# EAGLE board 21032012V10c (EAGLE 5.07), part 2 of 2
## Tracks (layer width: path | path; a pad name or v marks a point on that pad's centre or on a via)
ADJ2  (via drill 1)
  Top 0.406: 22.23,62.23 V-SO8.4 21.78,63.65 | 31.55,74.3 33.02,74.93 | V-1083.1 36.17,74.24 35.56,82.23 33.28,84.75 C-MABDT1.1 | V-TO3.2 19.68,74.3
  Top 0.813: 22.23,62.23 TO92S.1 | 21.78,63.65 VR6.2 19.2,63.65 18.41,62.87 16.75,62.87 VPOT1.S | 33.28,84.75 VC2X.+
  Top 1.27: v40.64,74.61 39.37,73.03 | 19.68,74.3 31.55,74.3 | v22.37,76.39 V-TO3.2
  Bottom 0.406: 39.91,72.3 V-1083.1 V-TS.1 | 39.91,72.3 39.37,72.83 | 39.91,72.3 40.64,73.03 v40.64,74.61 41.27,74.93
  Bottom 0.813: VPOT1.S VPOT2.S 17.46,62.55 18.35,63.44
  Bottom 1.27: 18.35,63.44 arc30 22.23,73.66 v22.37,76.39
  pour Bottom (isolate 0.813, hatched): 39.37,76.83 43.18,76.83 43.18,69.22 41.91,67.94 39.37,67.94
  pour Top (isolate 0.813, hatched): 43.18,76.83 43.18,69.22 42.55,68.58 40.01,68.58 39.37,69.22 arc23 34.92,73.03 29.21,74.3 34.29,76.2 34.29,78.11 33.34,88.27 36.83,86.36 36.83,78.74 38.73,76.83
ADJUST  (via drill 0.6, 1)
  Top 0.406: 27.53,37.21 CR2.1 | V-TO1.2 19.22,34.29 v17.72,32.07 18.41,31.11 | 29.21,36.83 C-SO8.4 | 29.21,35.56 29.21,36.83 | 9.62,31.68 8.98,31.68 C.A | C.A C..A A.A 6.35,31.11 CD31.A | 29.21,36.83 28.57,36.83 | 29.21,35.56 29.21,33.66 | C-TO92.1 29.21,35.56 | CD4.1 10.96,29.68 9.53,31.11 9.53,31.14 C.A
  Top 0.813: C-1083.1 35.63,34.87 C.1.A | C-MABDT.1 31.49,47.25 33.66,45.09 33.66,42.55 C.1.A | C.1.A 36.65,41.27 38.73,41.27 38.99,41.02 C_REG_Q.E
  Top 1.016: 27.53,37.21 28.57,37.21 28.57,36.83
  Top 1.27: v29.21,28.26 26.67,28.51 arc-33 18.41,31.11
  Bottom 0.406: C-1083.1 39.5,32.38 | 29.72,33.85 C-TO92.1
  Bottom 0.813: 29.72,30.54 29.72,33.85
  Bottom 1.27: C-TS.1 C-1083.1 39.37,31.75 37.47,31.75 arc37 29.91,29.34 29.72,29.15 | v29.21,28.26 29.21,28.64 29.72,29.15 | 29.72,29.15 29.72,30.54
  pour Bottom (isolate 0.813, hatched): 19.68,32.38 arc-90 17.78,30.48 4.45,30.48 3.81,31.75 3.81,33.66 5.08,34.92 10.79,34.92 11.43,35.56 19.68,35.56
  pour Top (isolate 0.61): 29.84,39.37 20.95,39.37 20.95,36.83 28.57,36.2 29.21,35.56 29.84,35.56
B
  Top 0.406: VR48.1 78.72,15.9 | VR48.1 78.75,14.59 79.38,13.97 TRIM10X.S | VR48.1 VR47.2 VR49.2 | Q14.B 73.97,25.72 74.3,25.4 74.3,20.95 74.93,20.32 75.56,20.32 76.2,19.68 76.2,18.41 77.47,17.14 77.47,16.2 VR48.1
B1
  Bottom 0.406: 42.55,8.89 44.07,9.97 44.07,35.37 42.55,36.2 42.16,36.2 C_REG_Q.B
  Bottom 0.61: 42.55,8.89 33.66,8.89 32.38,7.62 27.94,7.62 26.67,8.89 13.97,8.89 11.43,11.43 CTRIM3.S R22.S
B-Q1
  Top 0.406: FC5.2 267.33,22.71 Q4.B 266.06,24.62 266.06,29.21 266.7,29.84 R8.2
BATT-  (via drill 0.6)
  Top 0.406: PS16.2 67,92.88 66.84,92.88 66.04,92.08 66.04,90.94 PS_TOP.2 65.91,88.39 v66.04,88.27 | v84.45,91.44 PS_ZEN_FB.A | P_Q11.2 v114.3,79.5 114.3,80.64 113.44,81.51 P_Q2.3 | P_C6.A 105.12,89.34 P_C10.- | v273.37,23.5 273.69,22.86 273.69,19.68 272.73,18.73 T1.2 272.73,15.4 FR12.2 | VENT_RB.2 103.35,79.86 v102.23,78.74 D11.A | D41.A 258.44,6.99 MINUS0S.1 | Q23.3 252.47,42.8 252.73,42.55 Q28.E | DR15.A 152.88,84.61 153.03,84.45 154.31,84.45 155.57,83.19 155.57,81.92 156.21,81.28 158.62,81.28 DC7.2
  Top 0.61: IC1.8 U$2.2 | DISP_Z.A 121.49,80.85 120.02,79.38 114.43,79.38 v114.3,79.5
  Bottom 0.406: v66.04,88.27 66.04,81.28 67.31,80.64 84.45,80.64 v84.45,91.44 | 114.3,80.64 118.75,80.64 118.75,79.38 121.28,76.83 263.52,76.83 | 114.3,80.64 106.05,80.64 | 106.05,80.64 102.23,80.64 v102.23,78.74 | 114.3,80.64 v114.3,79.5 | P_C10.- 106.05,89.53 106.05,80.64 | 149.22,94.61 IC1.8 151.76,92.71 152.4,92.08 163.83,92.08 165.53,93.78 SP1.- | 149.22,94.61 149.22,88.27 147.61,86.65 DR15.A | 149.22,94.61 146.05,94.61 C9.- 144.15,93.98 142.88,92.71 | 263.52,23.5 v273.37,23.5
  Bottom 0.813: 102.23,80.64 84.45,80.64
  Bottom 1.27: MINUS0X1.1 MINUS0S.1
  Bottom 1.778: Q44.E Q28.E
  Bottom 2.54: S1.5 197.49,97.79 211.46,83.82 255.27,83.82 | MINUS60.1 256.62,95.33 255.27,93.34 255.27,83.82 | 255.27,83.82 263.52,76.83 263.52,23.5 263.52,9.53 260.35,6.35 MINUS0S.1 257.81,7.62 257.81,37.21 Q44.E
  pour Top (isolate 0.813): 252.09,44.45 255.91,44.45 257.81,42.55 257.81,36.83 257.18,36.2 252.73,36.2 252.09,36.83 252.09,43.81
  pour Bottom (isolate 0.813, rank 2, hatched): 64.77,97.16 64.77,80.64 66.67,78.74 168.91,78.74 170.18,80.01 170.18,98.42 168.91,99.69 67.31,99.69 65.41,97.79
D
  Top 1.27: F2.1B 270.76,50.55 R6.2 | Q5.3 R6.2 | R6.2 268.22,50.8 F2.1A
E2  (via drill 0.6)
  Top 0.406: 243.21,8.26 243.21,6.99 MINU1S.1 241.3,5.71 239.4,7.62 D23.A | 243.21,8.26 D48.C | VR45.1 243.21,8.26 | LED11.A 250.82,27.3 R24.2 | Q7.3 233.42,42.8 233.68,42.55 Q18.E
  Top 0.61: Q37.E 242.89,27.62 v242.57,27.94
  Bottom 0.61: v242.57,27.94 242.57,27.3 244.79,25.08
  Bottom 1.27: MINU1S.1 MINUS1X.1
  Bottom 1.778: Q43.E Q18.E
  Bottom 2.54: R24.2 247.01,27.3 244.79,25.08 243.84,24.13 243.84,8.26 241.3,5.71 | MINU1S.1 241.3,5.71 | Q43.E 236.85,39.37 238.76,37.47 238.76,7.62 239.4,6.99 240.03,6.99 241.3,5.71
  pour Top (isolate 0.813): 233.04,44.45 236.85,44.45 238.76,42.55 238.76,36.83 238.12,36.2 233.68,36.2 233.04,36.83 233.04,43.81
E3  (via drill 0.6)
  Top 0.406: VR34.1 225.43,8.26 224.16,6.99 | D39.A 220.34,6.99 MINUS2.1 224.16,6.99 | Q24.3 214.37,42.8 214.63,42.55 Q27.E | LED6.A 231.78,26.67 R18.2 | 224.16,6.99 D30.C
  Top 0.61: Q36.E 223.84,27.62 v223.52,27.94
  Bottom 0.61: 226.06,25.4 v223.52,27.94
  Bottom 1.27: MINUS2.1 MINUS2X1.1
  Bottom 1.778: Q42.E Q27.E
  Bottom 2.54: R18.2 227.97,27.3 226.06,25.4 224.79,24.13 224.79,8.89 222.25,6.35 MINUS2.1 219.71,7.62 219.71,37.47 217.81,39.37 Q42.E
  pour Top (isolate 0.813): 214,44.45 217.81,44.45 219.71,42.55 219.71,36.83 219.07,36.2 214.63,36.2 214,36.83 214,43.81
E4  (via drill 0.6)
  Top 0.406: 205.74,8.26 D46.C | 203.2,5.71 205.74,8.26 | 205.74,8.26 VR44.1 | D21.A 201.29,7.62 203.2,5.71 | MINUS3S.1 203.2,5.71 | Q8.3 195.32,42.8 195.58,42.55 Q17.E | LED10.A 212.72,26.67 R21.2
  Top 0.61: Q35.E 204.79,27.62 v204.47,27.94
  Bottom 0.61: v204.47,27.94 205.1,27.94 207.33,25.72
  Bottom 1.27: MINUS3X.1 MINUS3S.1
  Bottom 1.778: Q41.E Q17.E
  Bottom 2.54: R21.2 208.91,27.3 207.33,25.72 205.74,24.13 205.74,8.26 203.2,5.71 MINUS3S.1 200.66,7.62 200.66,37.47 198.75,39.37 Q41.E
  pour Top (isolate 0.813): 194.94,44.45 198.75,44.45 200.66,42.55 200.66,36.83 200.03,36.2 195.58,36.2 194.94,36.83 194.94,43.81
E5  (via drill 0.6)
  Top 0.406: LED5.A 193.04,25.25 R16.2 | VR33.1 186.69,8.26 186.37,7.94 | 186.37,7.94 184.15,5.71 MINUS4S.1 184.15,6.99 182.25,8.89 D37.A | D28.C 186.37,10.68 186.37,7.94 | Q25.3 176.27,42.8 176.53,42.55
  Top 0.61: Q34.E 186.38,27.62 v186.06,27.94
  Bottom 0.61: 188.28,25.72 v186.06,27.94
  Bottom 1.27: MINUS4X4.1 MINUS4S.1
  Bottom 1.778: Q40.E Q26.E
  Bottom 2.54: R16.2 189.87,27.3 188.28,25.72 186.69,24.13 186.69,8.26 184.78,6.35 184.78,5.71 MINUS4S.1 181.61,7.62 181.61,37.47 179.71,39.37 Q40.E
  pour Top (isolate 0.813): 175.9,44.45 179.71,44.45 181.61,42.55 181.61,36.83 180.97,36.2 176.53,36.2 175.9,36.83 175.9,43.81
E6  (via drill 0.6)
  Top 0.406: LED9.A 173.99,24.61 R13.2 | Q9.3 157.22,42.8 157.48,42.55 | Q33.E 167.32,28.25 v167,28.57
  Top 0.61: D19.A 163.19,6.99 MINUS5S.1 167.64,7.62 167.64,8.26 | 167.64,8.26 D44.C | 167.64,8.26 VR46.1
  Bottom 0.406: v167,28.57 167.64,28.57 169.54,26.67 173.35,26.67 R13.2
  Bottom 1.27: MINUS5X2.1 MINUS5S.1
  Bottom 1.778: Q39.E Q16.E
  Bottom 2.54: R13.2 170.81,27.3 167.64,24.13 167.64,8.26 166.37,6.99 165.74,6.99 165.1,6.35 MINUS5S.1 162.56,7.62 162.56,37.47 160.66,39.37 Q39.E
  pour Top (isolate 0.813): 156.84,44.45 160.66,44.45 162.56,42.55 162.56,36.83 161.93,36.2 157.48,36.2 156.84,36.83 156.84,43.81
E7  (via drill 0.6)
  Top 0.406: LED4.A 154.94,24.61 R14.2
  Top 0.61: Q32.E 148.28,27.62 v147.96,27.94 | D34.A 144.15,6.99 MINUS6S.1 149.22,8.26 | 149.22,8.26 D26.C | 149.22,8.26 VR35.1
  Bottom 0.61: 150.18,25.72 v147.96,27.94
  Bottom 1.27: MINUS6X2.1 MINUS6S.1
  Bottom 1.778: Q38.E Q22.E
  Bottom 2.54: R14.2 151.76,27.3 150.18,25.72 148.59,24.13 148.59,8.26 MINUS6S.1 143.51,7.62 143.51,37.47 141.6,39.37 Q38.E
  pour Top (isolate 0.813): 137.79,44.45 141.6,44.45 143.51,42.55 143.51,36.83 142.88,36.2 138.43,36.2 137.79,36.83 137.79,43.81
E8  (via drill 0.6)
  Top 0.406: D13.C 125.09,6.99 PLUS7+.1 129.54,7.62 129.54,8.26 | 129.54,8.26 D35.C | 129.54,8.26 VR36.1 | LED7.A 135.89,24.61 R5.2 | Q3.3 119.12,42.8 119.38,42.55
  Top 0.61: Q31.E 129.22,27.62 v128.91,27.94
  Bottom 0.61: 131.13,25.72 v128.91,27.94
  Bottom 1.27: MINUS8-.1 PLUS7+.1
  Bottom 1.778: Q21.E Q15.E
  Bottom 2.54: R5.2 132.72,27.3 131.13,25.72 129.54,24.13 129.54,7.62 PLUS7+.1 125.09,6.99 124.46,6.99 124.46,37.47 122.56,39.37 Q21.E
  pour Top (isolate 0.813): 118.75,44.45 122.56,44.45 124.46,42.55 124.46,36.83 123.83,36.2 119.38,36.2 118.75,36.83 118.75,43.81
E9  (via drill 0.6)
  Top 0.406: D18.A 106.05,7.62 MINUS9.1 110.49,7.62 110.49,8.26 | LED8X.A 117.47,26.67 R4.2 | 110.49,8.26 D14.C | 110.49,8.26 VR28.1 | Q2T.E 100.07,39.63
  Top 0.61: Q30.E 110.17,27.62 v109.86,27.94
  Bottom 0.61: v109.86,27.94 109.86,27.3 111.76,25.4
  Bottom 1.27: PLUS8+.1 MINUS9.1
  Bottom 1.778: Q2T.E Q29.E 103.5,39.37
  Bottom 2.54: R4.2 113.67,27.3 111.76,25.4 110.49,24.13 110.49,8.26 108.58,6.35 108.58,5.71 MINUS9.1 105.41,7.62 105.41,37.47 103.5,39.37
  pour Top (isolate 0.813): 99.69,44.45 103.5,44.45 105.41,42.55 105.41,36.83 104.78,36.2 100.33,36.2 99.69,36.83 99.69,43.81
GATE
  Top 0.406: Q5.1 268.23,35.78 R10.2 269.72,33.81 270.51,33.02 270.51,29.84 269.88,29.21 269.88,28.09 R9.1 269.24,27.94 268.61,27.3 Q4.C
HOT  (via drill 0.6)
  Top 0.406: Q6.C Q10.2 92.71,86.36 93.34,87 95.25,87 97.16,88.9 v97.16,89.53 P_L1.1 99.39,89.58 P_C6.C
  pour Top (isolate 0.813, hatched): 95.25,92.08 99.06,92.08 100.33,90.81 100.33,84.45 99.69,83.82 93.98,83.82 92.08,85.72 90.81,85.72 90.81,86.36 90.81,87 92.71,87 94.61,88.9 94.61,89.53 95.25,90.17
  pour Bottom (isolate 0.813, hatched): 95.25,92.08 99.06,92.08 100.33,90.81 100.33,84.45 99.69,83.82 93.98,83.82 92.08,85.72 90.81,85.72 90.81,86.36 90.81,87 92.71,87 94.61,88.9 94.61,89.53 95.25,90.17
IN+1
  Top 0.406: 25.1,82.22 V-TO3.1 31.11,81.28 C-MABDT1.3 | TO92S.3 26.04,62.23 26.04,63.5 V-SO8.1
  Top 0.813: 26.04,59.05 26.04,63.5
  pour Bottom (isolate 0.813, hatched): 43.18,64.14 43.18,59.05 36.07,58.93 37.34,64.01
  pour Top (isolate 0.813, rank 3, hatched): 26.67,100.33 26.67,88.27 30.8,85.72 32.7,78.74 21.59,78.74 18.41,76.83 18.41,71.75 26.04,71.75 29.53,66.74 30.35,65.91 arc139 40.64,64.14 43.18,64.14 43.18,59.05 27.3,59.05 26.04,58.42 26.04,64.14 arc90 22.23,67.94 18.1,68.26 15.24,70.17 15.24,80.01 17.14,81.92 19.68,82.55 arc32 23.5,100.33
  pour Bottom (isolate 0.813, rank 4): 29.21,79.38 15.88,79.38 15.88,81.28 19.68,85.09 23.5,100.97 26.67,100.97 26.67,87 27.94,85.72 31.75,85.72 31.75,80.64
IN-  (via drill 1.3)
  Top 2.54: v203.84,111.12 v40.64,111.12
  Bottom 0.406: 45.72,92.71 VR10.2 43.18,95.89 VIN(-).1
  Bottom 2.54: MINUS120.1 217.88,97.08 v203.84,111.12 | v40.64,111.12 VIN(-).1
  pour Bottom (isolate 0.813, rank 2): 35.56,100.97 46.35,100.97 47.62,98.42 47.62,90.81 35.56,90.81
  pour Top (isolate 0.813, hatched): 47.62,100.33 47.62,88.9 38.73,88.9 38.73,93.98 35.56,94.61 35.56,100.33
INPUT+  (via drill 1)
  Top 0.406: C-SO8.1 32.7,40.96 v30.54,41.91 V-TO1.1 | CC3.1 CD1.C | C-TO92.3 33.02,35.56 | C-SO8.1 33.02,38.73 | 33.02,38.1 C-SO8.1 | v30.48,49.78 C-MABDT.3
  Top 0.61: C_OPTN1.1 37.47,51.44
  Top 0.813: 33.02,38.1 33.02,35.56 33.02,33.66 | 37.47,51.44 C_HV_Q.E
  Bottom 1.27: C-1083.3 C-TS.3
  pour Top (isolate 0.61, rank 2, hatched): 33.66,52.7 26.67,52.7 26.04,44.45 21.59,44.45 21.59,40.64 22.86,40.64 23.5,40.01 31.75,40.01 31.75,39.37 33.66,39.37
  pour Bottom (isolate 0.813, rank 2, hatched): 43.18,50.8 33.02,52.7 27.94,52.7 27.94,46.35 20.95,41.27 20.95,38.73 22.86,36.83 22.86,34.29 20.95,31.11 20.95,20.32 29.84,20.32 37.47,16.51 41.27,16.51 41.27,23.5 31.11,23.5 25.4,27.3 25.4,37.47 26.67,38.73 33.66,41.27 33.66,48.26 43.18,48.9
  pour Top (isolate 0.813, rank 2): 38.1,20.32 42.55,20.32 42.55,8.26 38.1,8.26
MINUS
  Top 0.406: CTRIM3.A 16.38,12.7 8.89,12.7 8.43,13.16 8.45,20.13 8.45,23.05 8.89,23.5 CD49.C 9.32,24.97 10.16,24.13 10.64,24.13 CD4.2
  Bottom 0.406: R22.E 16.43,12.73 CTRIM3.A
N$1
  Bottom 0.406: 16.43,60.01 VPOT2.A | VPOT1.E 17.27,58.55
  Bottom 1.016: VPOT1.E 16.43,60.01
  Bottom 1.27: 17.27,58.55 V_OPTION.2
N$2
  Top 0.406: VR5.2 16.43,66.04 VPOT1.A 14.35,66.61 arc-135 13.34,71.75 VR4.2
  Bottom 0.813: 16.45,66.4 VPOT1.A
  Bottom 1.27: VPOT2.E 16.45,66.4
N$3
  Top 0.406: VTRIM1.E VR8.2
  Bottom 0.813: VTRIM1.E 28.89,76.83
  pour Bottom (isolate 0.813, rank 2, hatched): 32.38,78.11 32.38,76.2 33.34,74.93 27.3,74.93 26.67,75.56 26.67,78.11
N$4
  Bottom 0.406: VR1.1 28.85,69.53 28.85,71.16
  Bottom 0.813: 28.85,71.16 VTRIM1.A
  pour Bottom (isolate 0.813, rank 3, hatched): 32.38,73.66 31.11,69.22 29.21,67.31 26.67,67.94 26.67,73.03 27.3,73.66
N$5
  Bottom 0.406: 17.73,18.41 CTRIM3.E 16.43,17.75 R22.A
  Bottom 0.61: 21,17.74 19.68,18.41 17.73,18.41
  Bottom 0.813: CTRIM2.A 24.13,12.74 CTRIM2.S 21.59,17.14 21,17.74
N$6
  Top 0.813: CR3.1 24.2,20.17 CTRIM2.E
N$7
  Top 0.406: VR7.1 VR3.1
  Bottom 0.406: VR3.1 VC1.1 VC2.2
  pour Bottom (isolate 0.813, rank 3): 34.29,90.81 27.3,90.81 27.3,100.97 34.29,100.97
  pour Top (isolate 0.813, rank 4): 34.29,90.81 27.3,90.81 27.3,100.33 34.29,100.33
N$9
  Bottom 0.813: CC4.- 31.75,11.43 VIN(-)1.1
  pour Bottom (isolate 0.813): 28.57,14.61 37.47,14.61 37.47,9.53 33.66,9.53 32.38,8.26 29.21,8.26 28.57,8.89
  pour Top (isolate 0.813): 28.57,14.61 37.47,14.61 37.47,8.26 29.21,8.26 28.57,8.89
N$10
  Top 0.813: V_HV_Q.B 19.05,96.67 VR9.1 VD5.C
N$11
  Top 0.406: OK10X.2 87,22.23 86.36,22.86 83.82,22.86 82.55,21.59 82.55,21.44 VR14.1 79.7,20.8 LED10X.C
N$12
  Top 0.406: VR3.2 VR7.2 29.88,87.83 VD7.C
  Top 0.813: VR2.1 VR8.1 | V_OPTION.1 VR6.1
  Bottom 0.813: VR3.2 30.42,85.79 33.66,84.45 VR2.1 33.66,76.47 arc-77 22.29,63.06 21.78,63.06 20.38,61.59 V_OPTION.1
N$13
  Top 0.406: VD6.C 31.75,92.08 VD7.A
N$14
  Top 0.406: D10A.A 74.72,16.4 VR48.2 75.25,13.65 TRIM10X.A
N$15
  Top 0.406: Q14.C 73.03,22.38 VR11.1
N$16
  Top 0.406: VR28.2 121.92,8.26 123.19,9.53 123.19,15.24 123.83,15.88 123.83,19.36 OK8X.1
N$17
  Top 0.406: D10A.C 71.33,15.46 D10.A
N$18
  Top 0.406: T1.3 271.78,24.77 272.42,25.4 272.42,27.79 R9.2
N$19
  Top 0.406: R11.1 272.57,10.31 271.78,9.53 267.97,9.53 267.33,10.16 FD16.A
N$20
  Top 0.406: TRIM9X.A 95.25,12.06 93.98,13.34 93.98,15.55 VR51.1 94.3,17.89 D9A.A
N$21
  Top 0.406: R11.2 FR12.1 269.72,16.99 270.51,17.78 270.51,18.27 T1.1
N$22
  Top 0.61: 121.28,99.01 121.28,96.52 121.92,95.89 | 121.92,95.89 D_Q1.2 | DISP_R.1 121.77,95.73 121.92,95.89
  Top 0.813: P_L1.2 97.16,98.42 97.79,99.06 113.67,99.06 | 121.28,99.01 120.65,99.06 113.67,99.06 | 113.67,99.06 VENTI.1
  Bottom 0.406: VENTI.1 P_C10.+
N$23
  Top 0.406: VR13.2 83.19,8.26 84.45,9.53 84.45,15.24 85.09,15.88 85.09,20 OK10X.1
N$24
  Top 0.406: D8.A 86.79,14.83 D10A1.C
N$25
  Top 0.406: Q1T.B 76.2,24.77 75.72,23.65 VR11.2 76.2,22.23 77.47,20.32 77.47,18.73 VR49.1 | Q1T.B Q1.B | Q1T.B 76.2,42.56 Q10S.1
N$26
  Top 0.406: D15.A 112.83,16.4 VR54.1 113.35,13.65 TRIM8X.A
N$27
  Top 0.406: TRIM8X.E 121.28,13.34 121.28,15.56 VR53.1 121.6,17.57 D12.A
N$29
  Top 0.406: D15.C 109.42,15.46 D14.A
N$31
  Top 0.406: OK8X.2 125.09,22.23 124.46,22.86 120.17,22.86 VR29.1 120.02,21.59 118.75,20.32 117.63,20.32 LED8X.C
N$32
  Top 0.406: D13.A 125.09,15.24 125.73,15.88 125.73,17.89 D12.C
N$33
  Top 0.406: VR55.2 117.16,18.1 115.57,19.68 115.57,20.47 VR12.2 114.3,22.71 Q15.B | Q3.1 114.56,42.17 114.3,41.91 Q15.B | Q15.B Q21.B
N$34  (via drill 0.6)
  Top 0.406: 132.06,93.95 LED3.2
  Top 0.61: C9.+ 148.59,87 IC1.1 U$2.5 | D_Q1.3 130.81,98.09 v131.44,97.79 132.08,96.52 132.06,93.95
  Bottom 0.61: C9.+ 139.7,88.9 v131.44,97.79
N$35  (via drill 0.6)
  Top 0.406: DR17.2 134.14,78.59 134.62,78.11 167,78.11 170.18,81.28 170.18,96.52 169.54,97.16 v161.93,97.16
  Top 0.61: U$2.1 153.42,91.82 154.31,92.71 IC1.7
  Bottom 0.406: v161.93,97.16 154.94,97.16 154.31,96.52 IC1.7
N$36
  Top 0.406: IC1.6 156.84,96.52 156.21,97.16 149.22,97.16 | 149.22,97.16 139.85,97.16 DR18.2 | U$2.3 150.11,91.82 149.22,92.71 149.22,97.16
N$37  (via drill 0.6)
  Top 0.406: v141.6,79.38 140.49,79.38 VR19.2 | DISP_Z3.C 165.94,80.22 v167,81.28
  Top 0.61: U$2.4 147.7,89.79 146.69,91.44 143.51,91.44 139.7,87 139.7,80.49 VR19.2
  Bottom 0.406: IC1.5 163.19,94.61 164.47,95.89 168.91,95.89 170.18,95.25 170.18,81.28 168.91,80.01 | 168.91,80.01 167,78.11 142.24,78.11 v141.6,79.38 | v167,81.28 167.64,81.28 168.91,80.01
N$38
  Top 0.813: Q10.3 84.86,84.05 83.82,85.09 83.82,85.24 Q6.E 77.28,85.41 PS_EMIT.2
N$39
  Top 0.406: 89.07,89.11 88.04,89.94 89.53,91.44 | 89.07,89.11 Q10.1 | 89.53,91.44 90.84,91.44 | 90.84,91.44 91.44,91.44 | 90.84,91.44 L2.2 | Q6.B 84.14,87.31 86.36,89.53 88.64,89.53 89.07,89.11 | PSOK2.3 72.39,96.52 73.66,98.42 86.36,98.42 87,97.16 87,93.34 88.9,91.44 89.53,91.44
N$41
  Top 0.406: PSOK2.2 80.49,96.52 PSR23.2 84.18,96.67 PS_ZEN_FB.C
N$42
  Top 0.406: PSR22.2 78.89,91.29 78.74,91.44 78.74,92.08 78.11,92.71 78.11,93.67 PSOK2.1
N$43
  Top 0.406: L2.1 88.9,99.69 70.97,99.69 PS16.1 | PS16.1 68.1,96.52 | PS16.1 67.79,96.52 66.04,96.52 64.14,94.61 64.14,85.72 67.31,85.72 68.89,88.58 PS_TOP.1 PS_BOT.2
N$45
  Top 0.406: Q35.C 205.59,24.15 VR39.1
N$46
  Top 0.61: DISP_Z.C 124.89,91.16 DISP_R.2 125.42,91.44 D_Q1.1
N$47
  Top 0.813: DR17.1 131.29,83.15 LED3.1
N$48
  Top 0.61: DR18.1 136.37,91.03 LED3.3
N$49
  Top 0.813: VR19.1 137.01,84.09 LED3.4
N$50
  Top 0.406: Q16.B 152.4,22.71 VR25.2 151.92,22.07 153.67,20.32 153.67,19.05 154.31,18.41 VR61.2 | Q9.1 152.66,42.8 152.4,42.55 Q16.B | Q16.B Q39.B
N$51
  Top 0.406: Q17.B 190.5,22.23 VR26.2 190.65,21.44 192.41,19.68 192.41,19.05 193.04,18.41 VR67.2 | Q8.1 190.76,42.8 190.5,42.55 Q17.B | Q17.B Q41.B
N$52
  Top 0.406: VR73.2 230.19,18.1 229.87,18.41 229.87,19.84 VR27.1 227.48,23.01 228.6,24.13 Q18.B | Q7.1 228.86,42.8 228.6,42.55 Q18.B | Q43.B Q18.B
N$53
  Top 0.813: VENTI.2 111.12,88.9 P_Q2.2 P_Q11.3
N$54
  Top 0.406: CD31.C 6.35,25.4 6.99,25.4 8.26,27.73 CD49.A
N$55
  Top 0.406: D34.C 144.57,14.61 D33.A
N$56
  Top 0.406: D9.A 91.44,15.24 90.81,15.88 90.81,17.98 D9A.C
N$57
  Top 0.406: TRIM7X.E 140.65,13.65 VR56.1 141.18,16.4 D33.C
N$62
  Top 0.406: TRIM3-9.A 189.87,13.34 189.87,15.88 VR66.1 189.66,16.4 D27.A
N$63
  Top 0.406: TRIM3-9.E 197.8,13.65 VR65.1 198.32,16.4 D22.C
N$64
  Top 0.406: Q34.B 188.28,26.36 189.23,25.4 189.23,20.95 189.87,20.32 190.5,20.32 191.13,19.68 191.13,18.41 192.41,17.14 192.41,16.2 VR66.2 193.04,15.88 193.68,15.24 | TRIM3-9.S 193.68,15.24 | 193.68,15.24 194.31,15.88 VR65.2 VR67.1
N$65
  Top 0.406: Q31.B 131.12,25.72 131.44,25.4 131.44,20.95 132.08,20.32 132.72,20.32 133.35,19.68 133.35,18.41 134.62,17.14 134.62,16.2 VR57.2 134.62,15.88 136.33,15.3 | 136.33,15.3 136.53,15.24 TRIM7X.S | 136.33,15.3 136.59,15.3 137.16,15.88 VR56.2 139.06,16.19 139.06,17.14 138.75,17.46 VR58.1
N$66
  Top 0.406: TRIM5X.A 151.45,13.65 VR60.1 150.93,16.4 D25.A
N$67
  Top 0.406: Q31.C 130.18,22.38 VR20.1
N$68
  Top 0.406: D19.C 163.62,14.2 D20.A
N$69
  Top 0.406: 144.99,79.38 DISP_Z1.A 144.81,79.61 DR15.E
N$70
  Top 0.406: D21.C 201.72,14.83 D22.A
N$71
  Top 0.406: D26.A 147.53,15.46 D25.C
N$72
  Top 0.406: TRIM5X.E 159.7,13.65 VR59.1 160.22,16.4 D20.C
N$73
  Top 0.406: D28.A 186.26,14.61 D27.C
N$74
  Top 0.406: D29.C 223.34,16.69 224.16,15.88 D30.A
N$75
  Top 0.406: U$2.6 156.59,89.79 156.84,89.53 IC1.3 DC7.1 160.04,83.97 DISP_R1.2 162.2,83.61 DISP_Z3.A
N$76
  Top 0.406: DISP_R1.1 161.29,80.01 160.66,79.38 153.03,79.38 152.65,79.76 DR15.S
N$77
  Top 0.406: OK6X.2 163.19,21.59 162.08,22.71 VR30.1 158.12,20.95 157.63,20.48 LED4.C
N$78
  Top 0.406: OK4X.2 201.29,22.23 200.81,22.71 VR31.1 196.22,21.59 195.74,21.11 LED5.C
N$79
  Top 0.406: OK2X.2 239.4,22.23 238.76,22.86 234.95,22.86 234.31,22.23 | VR32.1 234.31,22.23 | 234.31,22.23 234.31,21.59 233.84,21.11 LED6.C
N$80
  Top 0.406: OK6X.1 160.66,20.32 161.93,19.05 161.93,15.88 161.29,15.24 161.29,9.53 160.02,8.26 VR35.2
N$81
  Top 0.406: VR33.2 198.12,8.26 199.39,9.53 199.39,15.24 200.03,15.88 200.03,19.05 198.75,20.32 OK4X.1
N$82
  Top 0.406: VR34.2 236.22,8.26 237.49,9.53 237.49,15.24 238.12,15.88 238.12,19.05 236.85,20.32 OK2X.1
N$83
  Top 0.406: DISP_Z2.A 143.92,82.12 DISP_Z1.C
N$84
  Top 0.813: C_HV_Q.B CR4.1 36.4,44.93 C.1.C
N$85
  Top 0.813: CR4.2 41.12,47.78 C_HV_Q.C | CR4.2 36.35,47.78 | C_OPTN1.2 36.2,47.78 CR4.2
  Bottom 1.778: C_VIN+.1 C_HV_Q.C
N$86
  Top 0.406: Q19.B 93.03,25.72 93.34,25.4 93.34,20.95 93.98,20.32 94.61,20.32 95.25,19.68 95.25,18.41 96.52,17.14 96.52,16.2 | 96.52,16.2 VR51.2 | 96.52,16.2 99.69,16.2 VR50.2 | VR50.2 VR15.1 | VR50.2 99.06,15.88 98.42,15.24 TRIM9X.S
N$87
  Top 0.406: VR52.2 95.25,22.23 | 95.25,22.23 96.52,20.95 96.52,19.69 VR15.2 | 95.25,22.23 Q2T.B | Q2T.B 95.25,41.93 Q2S.1 | Q2T.B Q29.B
N$88
  Top 0.406: D36.A 131.88,16.4 VR57.1 132.4,13.65 TRIM7X.A
N$89
  Top 0.406: D37.C 182.68,14.83 D38.A
N$91
  Top 0.406: D35.A 129.54,14.61 128.27,15.88 128.27,18.21 D36.C
N$92
  Top 0.406: Q34.C 187.81,23.82 VR26.1
N$93
  Top 0.406: Q22.B 133.35,22.71 VR20.2 132.87,22.07 134.62,20.32 134.62,19.05 135.25,18.41 136.53,18.41 VR58.2 | Q20.1 133.61,42.8 133.35,42.55 Q22.B | Q22.B Q38.B
N$94
  Top 0.406: OK9X.2 106.05,22.23 105.41,22.86 102.23,22.86 101.45,22.07 VR24.1 99.37,20.48 LED9X.C
N$95
  Top 0.406: VR21.2 102.87,8.26 103.5,8.89 103.5,15.24 104.14,15.88 104.14,20 OK9X.1
N$96
  Bottom 0.406: SP1.+ 166.37,87.63 164.47,89.53 154.94,89.53 154.31,88.9 IC1.2
N$99
  Top 0.406: OK7.1 141.6,20.32 142.88,19.05 142.88,15.88 142.24,15.24 142.24,9.53 140.97,8.26 VR36.2
N$100
  Top 0.406: OK7.2 144.15,21.59 143.03,22.71 VR37.1 138.43,22.07 138.43,20.95 137.95,20.48 LED7.C
N$102
  Top 0.406: Q26.B 171.45,22.71 VR38.2 170.97,22.07 172.72,20.32 172.72,19.05 173.35,18.41 174.63,18.41 VR64.2 | Q25.1 171.71,42.8 171.45,42.55 Q26.B | Q26.B Q40.B
N$103
  Top 0.406: Q27.B 209.55,24.13 208.43,23.01 VR39.2 208.43,22.07 212.09,18.41 212.73,18.41 VR70.2 | Q24.1 209.81,42.8 209.55,42.55 Q27.B | Q27.B Q42.B
N$104
  Top 0.406: VR76.2 249.87,18.1 248.92,19.05 248.92,20.47 VR40.2 247.17,22.38 247.65,22.86 Q28.B | Q23.1 247.91,42.8 247.65,42.55 Q28.B | Q28.B Q44.B
N$105
  Top 0.406: Q32.B 150.18,25.72 150.5,25.4 150.5,20.95 151.13,20.32 151.76,20.32 152.4,19.68 152.4,18.41 153.67,17.14 153.67,16.2 | 153.67,16.2 VR60.2 | 155.57,15.24 156.21,15.88 VR59.2 VR61.1 | TRIM5X.S 155.57,15.24 | 153.67,16.2 153.99,15.88 154.94,15.88 155.57,15.24
N$106
  Top 0.406: TRIM2-7.A 170.5,13.65 VR63.1 169.97,16.4 D43.A
N$107
  Top 0.406: Q33.C 168.12,24.15 VR38.1
N$108
  Top 0.406: TRIM1-9.A 227.33,13.97 227.33,14.61 227.65,14.93 VR72.1 226.74,16.78 D29.A
N$109
  Top 0.406: TRIM2-9.E 216.85,13.65 VR68.1 217.38,16.4 D40.C
N$110
  Top 0.406: TRIM2-7.E 179.07,13.97 179.07,14.61 178.75,14.93 VR62.1 179.28,16.4 D38.C
N$111
  Top 0.406: Q33.B 169.22,25.72 169.54,25.4 169.54,20.95 170.18,20.32 170.81,20.32 171.45,19.68 171.45,18.41 172.72,17.14 172.72,16.2 | 172.72,16.2 VR63.2 | 174.62,15.24 175.26,15.88 VR62.2 VR64.1 | TRIM2-7.S 174.62,15.24 | 172.72,16.2 173.04,15.88 173.99,15.88 174.62,15.24
N$112
  Top 0.406: VR25.1 149.07,24.15 Q32.C
N$113
  Top 0.406: Q35.B 206.69,25.72 207.01,25.4 207.01,20.95 207.65,20.32 208.28,20.32 208.91,19.68 208.91,18.41 210.19,17.14 210.19,16.19 VR69.2 212.09,15.88 212.72,15.24 | TRIM2-9.S 212.72,15.24 | 212.72,15.24 213.36,15.88 VR68.2 VR70.1
N$115
  Top 0.406: TRIM2-9.A 208.6,13.65 VR69.1 207.63,16.84 D45.A
N$116
  Top 0.406: TRIM1-9.E 235.9,13.65 VR71.1 236.43,16.4 D24.C
N$118
  Top 0.406: D44.A 166.57,16.1 D43.C
N$119
  Top 0.406: D45.C 204.47,18.18 204.47,15.24 205.31,14.4 D46.A
N$120
  Top 0.406: D48.A 242.78,14.2 D47.C
N$121
  Top 0.406: OK5X.2 182.25,21.59 181.13,22.71 VR41.1 177.16,21.59 176.05,20.48 LED9.C
N$122
  Top 0.406: OK3.2 220.34,22.23 219.86,22.71 VR42.1 215.26,21.59 214.78,21.11 LED10.C
N$123
  Top 0.406: OK1X.2 258.44,22.23 257.96,22.71 VR43.1 251.77,21.11 LED11.C
N$124
  Top 0.406: OK5X.1 179.71,20.32 180.97,19.05 180.97,15.88 180.34,15.24 180.34,9.53 179.07,8.26 VR46.2
N$125
  Top 0.406: OK3.1 219.07,19.36 219.07,15.88 218.44,15.24 218.44,9.53 217.17,8.26 VR44.2
N$126
  Top 0.406: VR45.2 255.27,8.26 256.54,9.53 256.54,15.24 257.18,15.88 257.18,19.05 255.91,20.32 OK1X.1
N$127
  Top 0.406: TRIM9X.E 101.6,12.06 102.23,12.7 102.23,15.55 VR50.1 101.92,16.82 102.23,17.14 102.23,17.89 D17.C
N$128
  Top 0.406: TRIM10X.E VR47.1 83.39,16.4 D8.C
N$129
  Top 0.406: D18.C 106.05,17.89 D17.A
N$130
  Top 0.406: Q30.C 111.12,22.38 VR12.1
N$131
  Top 0.406: VR52.1 91.92,24.15 Q19.C
N$132
  Top 0.406: Q30.B 112.08,25.72 112.39,25.4 112.39,20.95 113.03,20.32 113.67,20.32 114.3,19.68 114.3,18.41 115.57,17.14 115.57,16.2 | 115.57,16.2 VR54.2 | 115.57,16.2 117.16,16.2 117.47,15.88 | TRIM8X.S 117.47,15.88 | 117.47,15.88 VR53.2 VR55.1
N$133
  Top 0.406: D40.A 220.98,17.89 220.98,14.61 220.78,14.4 D39.C
N$134
  Top 0.406: Q36.B 225.74,25.72 226.06,25.4 226.06,20.95 226.69,20.32 227.33,20.32 227.97,19.68 227.97,18.41 229.24,17.14 229.24,16.19 VR72.2 231.14,15.88 231.78,15.24 | VR71.2 | VR71.2 VR73.1 | VR71.2 232.41,15.88 231.78,15.24 | TRIM1-9.S 231.78,15.24
N$137
  Top 0.406: D23.C 239.82,14.2 D24.A
N$140
  Top 0.406: Q36.C 224.64,24.15 VR27.2
N$141
  Top 0.406: TRIM0-9.A 246.7,13.65 VR75.1 246.18,16.4 D47.A
N$142
  Top 0.406: D42.C 255.27,17.89 255.27,15.88 VR74.1 254.63,15.56 254.63,12.7 254,12.06 TRIM0-9.E
N$143
  Top 0.406: Q37.B 244.79,26.36 245.75,25.4 245.75,20.95 246.38,20.32 247.01,20.32 247.65,19.68 247.65,18.41 248.92,17.14 248.92,16.2 VR75.2 250.19,15.88 250.82,15.24 | VR76.1 VR74.2 251.46,15.88 250.82,15.24 | TRIM0-9.S 250.82,15.24
N$144
  Top 0.406: D42.A 259.08,17.89 259.08,13.97 258.88,13.77 D41.C
N$145
  Top 0.406: Q37.C 243.84,22.23 VR40.1
OUT1  (via drill 0.6)
  Top 0.406: 33.02,23.44 V-TO1.3 | C-1083.2 35.83,26.04 V-TO1.3 | C-TO92.2 31.11,34.29 31.75,33.66 C-SO8.7 31.75,31.11 31.43,30.8 | 26.99,32.7 CR2.2 | 31.43,30.8 31.11,30.48 V-TO1.3 | C-MABDT.4 19.05,49.53 CD1.A CC3.2 | CR5.2 23.61,34.48 | 31.11,31.11 31.43,31.11 31.43,30.8
  Top 0.813: 30.48,31.11 31.11,31.11 31.11,38.1
  Bottom 0.406: 13.59,41.4 13.34,43.18 13.34,45.09 | A..C.A 13.59,41.4 | C-TO92.2 31.11,34.23 31.75,33.28 34.23,33.28 | 37.53,38.04 38.16,38.67 | 13.59,41.4 CC3.2
  Bottom 1.27: 38.16,38.67 C_REG_Q.C
  other vias: 24.77,50.8 22.23,50.8 22.23,48.26 24.77,48.26
  pour Top: 26.67,46.35 19.68,46.35 arc-90 17.78,44.45 arc-64 10.16,45.09 9.53,46.99 3.81,47.62 3.81,52.7 26.67,52.7
  pour Bottom (isolate 0.813, hatched): 41.91,26.67 40.64,26.67 38.1,29.21 38.1,29.84 37.47,30.48 33.02,30.48 36.2,33.02 36.83,33.66 36.83,36.2 38.1,37.47 39.37,38.1 39.18,39.56 30.35,39.56 arc74 26.16,35.88 26.16,26.1 arc33 36.83,22.23 37.47,22.23
  pour Top (isolate 0.813, rank 3, hatched): 10.79,45.09 19.05,45.09 19.68,37.47 22.86,34.92 31.11,34.29 38.1,27.3 37.47,22.86 37.47,15.88 29.21,15.88 28.57,19.05 21.59,23.5 13.34,26.67 10.79,29.21
  pour Bottom (rank 3): 26.67,46.35 19.68,40.01 15.88,36.2 11.43,36.2 11.43,41.91 9.53,45.72 3.81,45.72 3.81,52.7 26.67,52.7
  pour Bottom (rank 3): 37.47,18.41 37.47,15.88 29.21,15.88 29.21,19.05 36.83,19.05
OUT2  (via drill 0.6)
  Top 0.406: 24.13,59.05 24.07,59.05 V-SO8.7 | 23.2,65.91 VR5.1 | C-MABDT1.4 v39.37,81.92
  Top 0.813: 24.13,59.05 TO92S.2 24.13,65.41 23.2,65.91 | VR5.1 23.01,67.79 22.86,67.94 18.41,67.94 17.14,69.22 14.29,69.22 VR1.2
  Bottom 0.406: V-1083.2 40.2,66.41
  Bottom 1.27: V-1083.2 V-TO3.3 36.01,70.55
  other vias: 41.27,81.92 41.27,83.82 39.37,83.82
  pour Bottom (isolate 0.813, rank 6, hatched): 38.73,64.14 36.83,62.87 35.56,62.87 35.56,62.23 31.11,55.24 31.11,54.61 12.7,54.61 10.79,57.15 10.79,73.66 12.7,78.74 11.43,83.82 3.81,83.82 3.81,100.97 14.61,100.97 18.41,93.34 19.68,90.17 17.78,84.45 14.61,79.38 14.61,57.15 25.08,60.96 27.94,63.18 31.11,66.67 33.02,69.85 34.29,74.3 34.92,76.2 34.92,86.68 47.62,86.68 47.62,77.91 38.73,77.79
  pour Top (isolate 0.254, rank 2, hatched): 17.14,81.92 11.43,81.92 11.43,83.82 3.81,83.82 3.81,97.16 14.61,97.16 18.41,93.34 19.68,90.17
OUT+
  Top 0.406: A.C C..C C.C
  pour Bottom (isolate 0.813, rank 2, hatched): 10.16,36.2 3.81,36.2 3.81,46.35 8.26,46.35 10.16,42.55
PLUS10  (via drill 0.6)
  Top 0.406: D10A1.A 86.36,7.62 MINUS10.1 89.53,5.08 91.44,6.99 91.44,8.26 | 91.44,8.26 D9.C | 91.44,8.26 VR21.1 | Q19.E 91.12,28.25 v90.81,28.57 | LED9X.A 98.42,26.67 R3.2
  Bottom 0.406: MINUS10.1 89.53,5.08
  Bottom 0.61: 90.81,23.5 v90.81,28.57
  Bottom 1.27: PLUS9.1 MINUS10.1
  Bottom 1.778: Q1.E Q1T.E
  Bottom 2.54: Q1.E 86.36,37.72 86.36,7.62 MINUS10.1 90.81,7.62 90.81,23.5 94.61,27.3 R3.2
  pour Top (isolate 0.813): 80.64,44.45 84.45,44.45 86.36,42.55 86.36,36.83 85.72,36.2 81.28,36.2 80.64,36.83 80.64,43.81
PLUS11  (via drill 0.6, 1.3)
  Top 0.406: LED10X.A 79.38,26.67 R2.2 | Q14.E 71.92,26.5 v71.12,27.94 | FD16.C FC5.1 267.84,17.65 269.24,19.05 269.24,21.59 269.88,22.23 269.88,22.71 Q4.E 269.56,23.18 270.51,24.13 270.51,25.4 271.14,26.04 271.14,29.21 271.78,29.84 271.78,30.96 R7.1 271.93,31.9 273.05,33.02 273.05,33.81 R10.1 272.57,37.52 Q5.2 | PSOK2.4 72.39,93.98 73.97,92.39 PS_BOT.1 PSR22.1 76.05,89.69 | 76.05,89.69 76.83,88.27 81.28,88.27 81.28,92.71 80.64,93.34 PSR23.1 | 74.17,86.36 74.17,88.14 v74.3,88.27 76.05,89.69 | 74.17,86.36 PS_EMIT.1 | VENT_RT.1 75.56,80.64 74.3,81.28 74.17,86.36 | 72.39,8.26 72.39,7.62 PLUS10.1 | 72.39,8.26 D10.C | 72.39,8.26 VR13.1 | DISP_Z2.C 143.94,85.52 v143.95,85.66
  Top 2.54: 272.57,37.52 277.5,42.6 277.5,73.66 269.88,80.01 v173.99,80.01
  Bottom 0.406: 179.86,96.52 S1.2 | v143.95,85.66 127.64,85.72 126.36,87 126.36,102.23 | 65.41,102.23 74.3,102.23 v74.3,88.27
  Bottom 0.813: 71.75,24.13 71.75,27.3 v71.12,27.94
  Bottom 1.27: PLUS10.1 PLUS10+.1
  Bottom 2.54: S1.2 180.34,97.79 175.9,102.23 126.36,102.23 65.41,102.23 60.33,97.16 60.33,13.97 69.22,5.08 PLUS10.1 69.85,5.71 71.75,6.35 71.75,24.13 72.39,24.13 75.56,27.3 R2.2 | v173.99,80.01 173.99,93.34 177.16,96.52 179.86,96.52
Q0C
  Top 0.406: Q44.C 250.19,32.38 253.37,29.21 VR43.2
  pour Bottom (isolate 0.813, hatched): 259.08,74.3 259.08,40.01 241.3,40.01 241.3,74.3
  pour Top (isolate 0.813, hatched): 259.08,74.3 259.08,45.72 241.3,45.72 241.3,74.3
Q1C
  Top 0.406: VR14.2 81.92,30.48 78.74,34.29 Q1.C
  pour Top (isolate 0.813, hatched): 87.63,74.3 88.27,45.72 69.85,45.72 69.85,74.3
  pour Bottom (isolate 0.813, hatched): 87.63,74.3 87.63,40.01 69.85,40.01 69.85,74.3
Q2C
  Top 0.406: Q43.C 231.14,31.75 234.31,28.57 VR32.2
  pour Bottom (isolate 0.813, hatched): 240.03,74.3 240.03,40.01 222.25,40.01 222.25,74.3
  pour Bottom (isolate 0.813, hatched): 240.03,74.3 240.03,40.01 222.25,40.01 222.25,74.3
  pour Top (isolate 0.813, hatched): 240.03,74.3 240.03,45.72 222.25,45.72 222.25,74.3
Q3C
  Top 0.406: Q42.C 212.09,31.75 215.26,28.57 VR42.2
  pour Bottom (isolate 0.813, hatched): 220.98,74.3 220.98,40.01 203.2,40.01 203.2,74.3
  pour Top (isolate 0.813, hatched): 220.98,74.3 220.98,45.72 203.2,45.72 203.2,74.3
Q4C
  Top 0.406: Q41.C 193.04,32.38 196.22,29.21 VR31.2
  pour Bottom (isolate 0.813, hatched): 201.93,74.3 201.93,40.01 184.15,40.01 184.15,74.3
  pour Top (isolate 0.813, hatched): 201.93,74.3 201.93,45.72 184.15,45.72 184.15,74.3
Q5C
  Top 0.406: Q40.C 173.99,32.38 177.16,29.21 VR41.2
  pour Bottom (isolate 0.813, hatched): 182.88,74.3 182.88,40.01 165.1,40.01 165.1,74.3
  pour Top (isolate 0.813, hatched): 182.88,74.3 182.88,45.72 165.1,45.72 165.1,74.3
Q6C
  Top 0.406: Q39.C 154.94,33.02 158.12,29.84 VR30.2
  pour Bottom (isolate 0.813, hatched): 163.83,74.3 163.83,40.01 146.05,40.01 146.05,74.3
  pour Top (isolate 0.813, hatched): 163.83,74.3 163.83,45.72 146.05,45.72 146.05,74.3
Q7C
  Top 0.406: Q38.C 135.89,32.38 139.06,29.21 VR37.2
  pour Bottom (isolate 0.813, hatched): 144.78,74.3 144.78,40.01 127,40.01 127,74.3
  pour Top (isolate 0.813, hatched): 144.78,74.3 144.78,45.72 127,45.72 127,74.3
Q8C
  Top 0.406: Q21.C 116.84,33.02 120.02,29.84 VR29.2
  pour Top (isolate 0.813, hatched): 125.73,74.3 125.73,45.72 107.95,45.72 107.95,74.3
  pour Bottom (isolate 0.813, hatched): 125.73,74.93 125.73,40.64 107.95,40.64 107.95,74.93
Q9C
  Top 0.406: VR24.2 100.97,29.84 97.79,33.02 Q29.C
  pour Bottom (isolate 0.813, hatched): 106.68,74.3 106.68,40.01 88.9,40.01 88.9,74.3
  pour Top (isolate 0.813, hatched): 106.68,74.3 106.68,45.72 88.9,45.72 88.9,74.3
V+OUT
  Top 0.406: R8.1 266.7,33.66 268.29,32.64 268.61,31.6 R7.2
  Top 0.813: R6.1 264.16,60.96 264.16,36.35 R8.1
  Bottom 0.406: VOUT(+)1.1 237.49,108.58 238.12,107.95
  Bottom 0.61: F2.2B 270.89,67.56 R6.1 268.35,67.94 F2.2A
  Bottom 2.54: PLUS120.1 237.62,107.44 238.12,107.95 240.03,109.86 269.88,109.86 275.59,104.14 275.59,81.92 270.51,76.83 R6.1
V-
  Top 0.813: VR1X.1 39.66,87.72 VCQ.B
  Top 1.778: VR1X.1 45,87.72 46.35,87 VR10.1 46.35,59.05 44.45,57.15 VOUT-.1
  Bottom 2.54: S1.4 190.98,109.37 189.23,111.12 53.34,111.12 51.44,109.22 51.44,64.14 44.45,57.15 VOUT-.1 37.47,57.15 37.08,57.53 VC1X.-
VENTB
  Top 0.305: OK1X.3 258.44,27.5 259.71,28.89 259.71,75.56
  Top 0.406: OK10X.3 87,28.57 88.27,29.84 88.27,74.3 90.81,76.83 107.31,76.83 | 105.89,82.55 VENT_RB.1 106.35,82.4 108.58,82.4 | OK9X.3 106.05,27.94 107.31,29.21 107.31,76.83 | 126.36,76.83 109.86,76.83 | 109.86,76.83 107.31,76.83 | 126.36,76.83 126.36,29.54 OK8X.3 | 259.71,75.56 257.81,76.83 240.66,76.83 | 183.51,76.83 202.56,76.83 | 202.56,76.83 221.62,76.83 | 221.62,76.83 240.66,76.83 | 183.51,76.83 165.1,76.83 | 165.1,76.83 145.48,76.83 | 145.48,76.83 126.36,76.83 | OK7.3 144.15,29.21 145.48,31.18 145.48,76.83 | OK6X.3 163.19,28.57 164.47,29.84 164.47,76.2 165.1,76.83 | OK5X.3 182.25,27.94 183.51,29.84 183.51,76.83 | OK4X.3 201.29,27.94 202.56,29.21 202.56,76.83 | OK3.3 220.34,27.94 221.62,29.21 221.62,76.83 | OK2X.3 239.4,27.94 240.66,29.21 240.66,76.83 | 109.86,76.83 110.17,77.16 P_Q11.1 109.69,79.55 108.58,80.64 108.58,82.4 | 108.58,82.4 P_Q2.1
VENTMID  (via drill 0.6)
  Top 0.406: v87.31,75.56 87.31,30.48 87,29.84 85.72,29.84 84.45,28.57 OK10X.4 | VENT_RT.2 93.98,78.59 95.1,78.59 v95.25,78.74 D11.C | OK9X.4 103.5,27.94 106.36,29.84 106.36,74.93 105.73,75.88 v105.66,75.56 | OK8X.4 122.56,29.21 125.41,33.02 125.41,74.93 v124.46,75.56 | OK1X.4 255.91,29.21 258.76,30.99 258.76,74.8 v256.54,75.56 | OK7.4 141.6,28.57 144.46,31.75 144.46,73.6 v143.38,75.56 | OK6X.4 160.66,27.94 163.51,30.54 163.51,74.3 162.94,75.18 v162.94,75.63 | OK5X.4 179.71,28.57 182.56,31.05 182.56,73.66 v182.05,75.5 | OK4X.4 198.75,27.94 201.61,30.48 201.61,73.66 v201.04,75.56 | OK3.4 217.81,27.94 220.66,30.48 220.66,73.66 v220.09,75.56 | OK2X.4 236.85,28.57 239.71,31.11 239.71,73.66 v239.08,75.56
  Bottom 0.406: 95.25,75.56 v87.31,75.56 | 95.25,75.56 v95.25,78.74 | 95.25,75.56 v105.66,75.56 v124.46,75.56 v143.38,75.56 163.19,75.56 | 182.25,75.56 v201.04,75.56 v220.09,75.56 v239.08,75.56 v256.54,75.56 | 182.25,75.56 163.19,75.56 | 163.19,75.56 v162.94,75.63 | v182.05,75.5 182.25,75.56
VIN+  (via drill 1.3)
  Top 0.406: VR9.2 21.74,94.13 VIN(+).1
  Top 1.778: 21.59,101.6 V_HV_Q.C
  Top 2.54: v189.87,83.82 177.16,83.82 173.99,87 173.99,104.14 171.45,106.68 26.67,106.68 21.59,101.6
  Bottom 1.27: V_HV_Q.C VIN(+).1
  Bottom 2.54: VIN(+).1 VIN+1.1 | S1.6 190.98,84.94 v189.87,83.82
VIRT-
  Top 0.406: D2.C 35.67,92.39 VD6.A
  Top 0.813: VC2X.- D2.C 36.83,88.9 VCQ.C
  Bottom 0.813: C3.- 26.67,87.63 28.57,89.53 31.11,89.53 31.75,90.17 33.18,90.17 VC2X.-
  pour Top: 36.2,93.98 37.47,92.08 38.1,88.27 35.56,88.27 33.02,90.17 34.92,92.08 34.92,93.98
  pour Bottom: 36.2,93.98 38.1,92.08 38.1,88.27 35.56,88.27 33.02,90.17 34.92,92.08 34.92,93.98
VOUT+REG
  Bottom 2.54: S1.1 178.23,105.61 177.16,106.68 60.96,106.68 55.88,101.6 55.88,62.23 46.99,53.34 VOUT(+)REG.1
  pour Top (isolate 0.813, hatched): 43.18,52.07 38.73,52.07 arc25 33.02,53.98 31.11,54.61 12.7,54.61 arc-73 3.81,66.67 3.81,80.64 13.97,80.64 11.43,67.94 15.24,65.41 15.24,58.42 19.05,57.15 34.92,57.15 43.18,54.61

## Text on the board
Top: 14042012 | MICHAEL5.net
Bottom: MICHAEL5.net | 14042012
tNames: V_out(+) | V_in(+)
